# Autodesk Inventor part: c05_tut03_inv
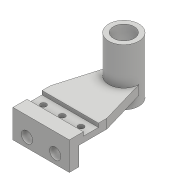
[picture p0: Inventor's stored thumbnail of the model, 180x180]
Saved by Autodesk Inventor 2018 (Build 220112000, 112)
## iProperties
Created: 2017-04
Part Number: c05_tut03_inv
Material: Generic
Document SubType Name: Modeling
Designer: CADCIM 00
Density: 1 g/cm^3
Appearance: Default
Author: CADCIM 00
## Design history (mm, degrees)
sketch "Sketch1"
  geometry: L1 (0, 0)-(-9, 0); L2 (-9, 0)-(-9, -4); L3 (-9, -4)-(-25, -4); L4 (-25, -4)-(-25, 0); L5 (-25, 0)-(-40, 0); L6 (-40, 0)-(-40, -30); L7 (-40, -30)-(-30, -30); L8 (-30, -30)-(-30, -10); L9 (-30, -10)-(0, -10); L10 (0, -10)-(0, 0)
  constraints: 20 end point, 7 perpendicular, 2 point on line, 1 horizontal, 1 vertical
  dimensions: "d0" = 4 distance of L1.end L2.end; "d1" = 16 distance of L2.end L3.end; "d3" = 15 distance of L4.end L5.end; "d4" = 30 distance of L5.end L6.end; "d5" = 10 distance of L6.end L7.end; "d6" = 10 distance of L9.end L1.start; "d7" = 40 distance between parallel lines of L10 L6
extrude "Extrusion1" new body sketch "Sketch1" stored distance "d8" = 60; taper "d9" = 0 deg
sketch "Sketch2"
  geometry: L1 (0, 9)-(60, 9) reference; L2 (0, 9)-(14, 57); L3 (14, 57)-(46, 57); L4 (46, 57)-(60, 9); L5 (60, 9)-(0, 9); L6 (30, 9)-(30, 57)
  constraints: 10 end point, 2 parallel, 1 midpoint, 1 vertical
  dimensions: "d10" = 48 distance between parallel lines of L3 L1; "d11" = 32 distance of L2.end L3.end
extrude "Extrusion2" join sketch "Sketch2" distance "d12" = 10; taper "d13" = 0 deg
workplane "Work Plane1"
sketch "Sketch3"
  geometry: L1 (46, 78)-(14, 78) reference; 2 further points
  constraints: 1 horizontal alignment, 1 midpoint, 2 other
extrude "Extrusion3" join sketch "Sketch3" distance "d15" = 60; taper "d16" = 0 deg
sketch "Sketch4"
  geometry: C1 r 11 at (0, 0); 1 further point
  constraints: 1 centre point
  dimensions: "d17" = 22 diameter of C1
extrude "Extrusion4" cut sketch "Sketch4" distance "d18" = 60; taper "d19" = 0 deg
sketch "Sketch5"
  geometry: L1 (0, 0)-(0, 16) reference; L2 (0, -15)-(60, -15) reference; C1 r 3 at (10, 7.5); C2 r 3 at (30, 7.5); C3 r 3 at (50, 7.5); 1 further point
  constraints: 3 centre point, 2 equal radius, 2 horizontal alignment
  dimensions: "d20" = 6 diameter of C1; "d21" = 10 distance from line of L1 C1.centre; "d22" = 20 distance of C1.centre C2.centre; "d24" = 22.5 distance from line of L2 C1.centre; "d33" = 20 distance of C3.centre C2.centre
extrude "Extrusion5" cut sketch "Sketch5" distance "d25" = 60; taper "d26" = 0 deg
sketch "Sketch6"
  geometry: L1 (0, 0)-(0, 30) reference; L2 (0, 0)-(60, 0) reference; C1 r 6 at (15, 10); C2 r 6 at (45, 10); 1 further point
  constraints: 2 centre point, 1 equal radius, 1 horizontal alignment
  dimensions: "d27" = 15 distance from line of L1 C1.centre; "d28" = 12 diameter of C1; "d29" = 30 distance of C2.centre C1.centre; "d30" = 10 distance from line of L2 C1.centre
extrude "Extrusion6" cut sketch "Sketch6" stored distance "d31" = 60; taper "d32" = 0 deg
body "Solid1"
